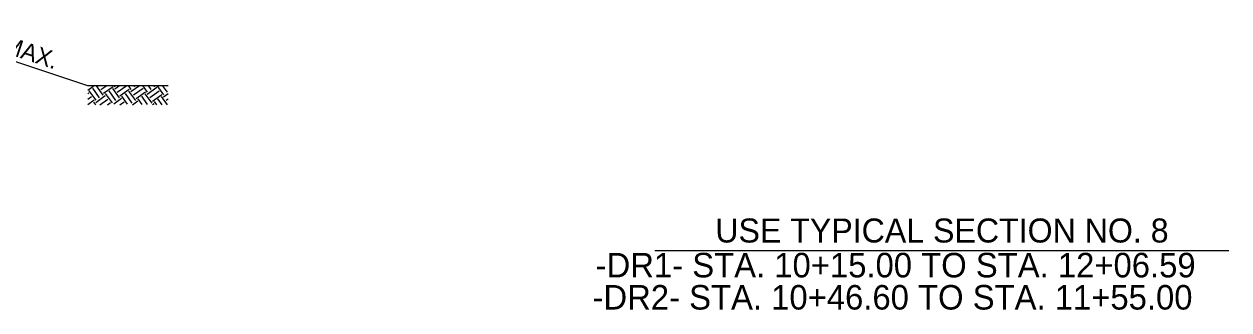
# Model space of a CAD drawing. Extents: x 3025871 to 3026431, y 707165 to 707825.
# Drawn here: x 3026178.1 to 3026263.1, y 707165.3 to 707185.5 of the extents above; entities that cross this region are included whole.
import ezdxf

# ---------------------------------------------------------------- set-up
doc = ezdxf.new("R2010")
doc.units = 0
doc.layers.add('Prop Drainage Structure Junction Box with Slab Lid TB 840 34 CELL', color=7, linetype='Continuous')
doc.layers.add('Typical Text Grade Point CELL', color=7, linetype='Continuous')

msp = doc.modelspace()

# ---------------------------------------------------------------- linework, layer by layer
at = {"layer": 'Prop Drainage Structure Junction Box with Slab Lid TB 840 34 CELL'}
msp.add_line((3026222.627, 707169.519), (3026263.131, 707169.519), dxfattribs=at)
at = {"layer": 'Typical Text Grade Point CELL'}
for p, q in [((3026169.573, 707185.497), (3026182.573, 707181.164)), ((3026182.573, 707181.164), (3026188.257, 707181.164)), ((3026182.573, 707181.164), (3026188.257, 707181.164)), ((3026182.594, 707180.834), (3026183.054, 707181.165)), ((3026182.594, 707180.834), (3026183.054, 707181.165)), ((3026183.434, 707180.297), (3026182.954, 707180.966)), ((3026183.434, 707180.297), (3026182.954, 707180.966)), ((3026183.685, 707180.477), (3026183.204, 707181.146)), ((3026183.685, 707180.477), (3026183.204, 707181.146)), ((3026183.348, 707181.122), (3026183.408, 707181.166)), ((3026183.348, 707181.122), (3026183.408, 707181.166)), ((3026183.528, 707180.872), (3026183.939, 707181.167)), ((3026183.528, 707180.872), (3026183.939, 707181.167)), ((3026183.708, 707180.621), (3026184.376, 707181.101)), ((3026183.708, 707180.621), (3026184.376, 707181.101)), ((3026184.833, 707180.289), (3026184.353, 707180.958)), ((3026184.833, 707180.289), (3026184.353, 707180.958)), ((3026184.52, 707181.078), (3026184.455, 707181.169)), ((3026184.52, 707181.078), (3026184.455, 707181.169)), ((3026184.497, 707180.934), (3026184.824, 707181.17)), ((3026184.497, 707180.934), (3026184.824, 707181.17)), ((3026184.677, 707180.684), (3026185.345, 707181.164)), ((3026184.677, 707180.684), (3026185.345, 707181.164)), ((3026184.857, 707180.433), (3026185.525, 707180.913)), ((3026184.857, 707180.433), (3026185.525, 707180.913)), ((3026185.669, 707180.89), (3026185.466, 707181.171)), ((3026185.669, 707180.89), (3026185.466, 707181.171)), ((3026185.645, 707180.746), (3026186.24, 707181.174)), ((3026185.645, 707180.746), (3026186.24, 707181.174)), ((3026185.825, 707180.495), (3026186.494, 707180.976)), ((3026185.825, 707180.495), (3026186.494, 707180.976)), ((3026185.919, 707181.07), (3026185.846, 707181.173)), ((3026185.919, 707181.07), (3026185.846, 707181.173)), ((3026186.818, 707180.702), (3026186.486, 707181.164)), ((3026186.818, 707180.702), (3026186.486, 707181.164)), ((3026186.794, 707180.558), (3026187.462, 707181.038)), ((3026186.794, 707180.558), (3026187.462, 707181.038)), ((3026187.068, 707180.882), (3026186.857, 707181.175)), ((3026187.068, 707180.882), (3026186.857, 707181.175)), ((3026187.319, 707181.062), (3026187.246, 707181.164)), ((3026187.319, 707181.062), (3026187.246, 707181.164)), ((3026187.966, 707180.514), (3026187.499, 707181.164)), ((3026187.966, 707180.514), (3026187.499, 707181.164)), ((3026188.217, 707180.694), (3026187.879, 707181.164)), ((3026188.217, 707180.694), (3026187.879, 707181.164)), ((3026182.594, 707180.581), (3026182.679, 707180.642)), ((3026182.594, 707180.581), (3026182.679, 707180.642)), ((3026182.594, 707180.201), (3026182.86, 707180.391)), ((3026182.594, 707180.201), (3026182.86, 707180.391)), ((3026182.594, 707179.821), (3026183.04, 707180.141)), ((3026182.594, 707179.821), (3026183.04, 707180.141)), ((3026183.183, 707180.117), (3026182.703, 707180.785)), ((3026183.183, 707180.117), (3026182.703, 707180.785)), ((3026183.16, 707179.973), (3026183.828, 707180.454)), ((3026183.16, 707179.973), (3026183.828, 707180.454)), ((3026183.452, 707179.803), (3026184.008, 707180.203)), ((3026183.452, 707179.803), (3026184.008, 707180.203)), ((3026184.332, 707179.929), (3026183.852, 707180.597)), ((3026184.332, 707179.929), (3026183.852, 707180.597)), ((3026184.583, 707180.109), (3026184.102, 707180.778)), ((3026184.583, 707180.109), (3026184.102, 707180.778)), ((3026184.428, 707179.871), (3026184.977, 707180.266)), ((3026184.428, 707179.871), (3026184.977, 707180.266)), ((3026185.401, 707179.852), (3026185, 707180.409)), ((3026185.401, 707179.852), (3026185, 707180.409)), ((3026185.731, 707179.921), (3026185.251, 707180.589)), ((3026185.731, 707179.921), (3026185.251, 707180.589)), ((3026185.982, 707180.101), (3026185.502, 707180.77)), ((3026185.982, 707180.101), (3026185.502, 707180.77)), ((3026185.744, 707179.803), (3026186.126, 707180.078)), ((3026185.744, 707179.803), (3026186.126, 707180.078)), ((3026186.006, 707180.245), (3026186.674, 707180.725)), ((3026186.006, 707180.245), (3026186.674, 707180.725)), ((3026186.43, 707179.831), (3026186.149, 707180.221)), ((3026186.43, 707179.831), (3026186.149, 707180.221)), ((3026186.815, 707179.823), (3026186.4, 707180.401)), ((3026186.815, 707179.823), (3026186.4, 707180.401)), ((3026187.131, 707179.913), (3026186.65, 707180.582)), ((3026187.131, 707179.913), (3026186.65, 707180.582)), ((3026186.974, 707180.307), (3026187.643, 707180.788)), ((3026186.974, 707180.307), (3026187.643, 707180.788)), ((3026187.154, 707180.057), (3026187.823, 707180.537)), ((3026187.154, 707180.057), (3026187.823, 707180.537)), ((3026187.844, 707179.803), (3026187.549, 707180.213)), ((3026187.844, 707179.803), (3026187.549, 707180.213)), ((3026188.229, 707179.795), (3026187.799, 707180.393)), ((3026188.229, 707179.795), (3026187.799, 707180.393)), ((3026187.943, 707180.37), (3026188.257, 707180.596)), ((3026187.943, 707180.37), (3026188.257, 707180.596)), ((3026188.123, 707180.119), (3026188.257, 707180.216)), ((3026188.123, 707180.119), (3026188.257, 707180.216)), ((3026183.155, 707179.803), (3026183.016, 707179.997)), ((3026183.155, 707179.803), (3026183.016, 707179.997)), ((3026183.981, 707179.803), (3026184.188, 707179.953)), ((3026183.981, 707179.803), (3026184.188, 707179.953)), ((3026184.862, 707179.803), (3026185.157, 707180.015)), ((3026184.862, 707179.803), (3026185.157, 707180.015)), ((3026187.172, 707179.816), (3026187.274, 707179.89)), ((3026187.172, 707179.816), (3026187.274, 707179.89)), ((3026187.458, 707179.81), (3026187.298, 707180.033)), ((3026187.458, 707179.81), (3026187.298, 707180.033))]:
    msp.add_line(p, q, dxfattribs=at)

# ---------------------------------------------------------------- texts
at = {"layer": 'Prop Drainage Structure Junction Box with Slab Lid TB 840 34 CELL'}
for s, height, p in [('USE TYPICAL SECTION NO. 8', 1.69489, (3026226.885, 707170.081)), ('-DR1- STA. 10+15.00 TO STA. 12+06.59', 1.73151, (3026218.44, 707167.62)), ('-DR2- STA. 10+46.60 TO STA. 11+55.00', 1.73151, (3026218.219, 707165.35))]:
    msp.add_text(s, height=height, rotation=360, dxfattribs=at).set_placement(p)
at = {"layer": 'Typical Text Grade Point CELL'}
msp.add_text('2:1 MAX.', height=1.2089, rotation=341.56505, dxfattribs=at).set_placement((3026173.946, 707184.4))

doc.saveas('drawing.dxf')
